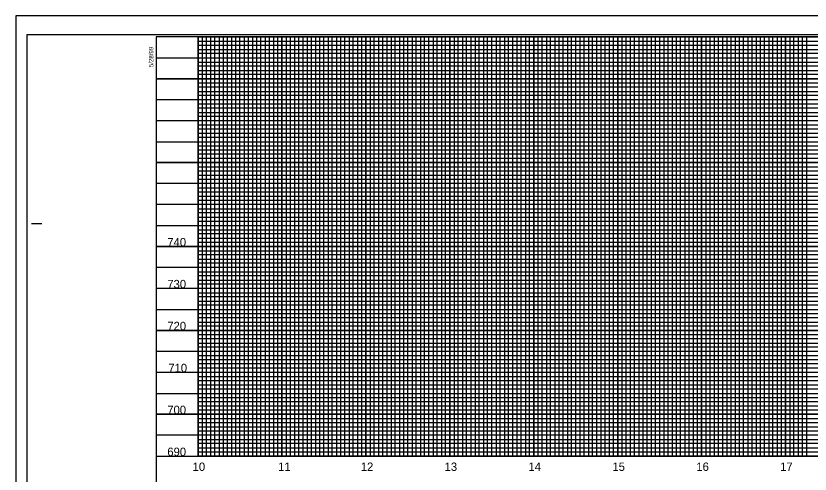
# Model space of a CAD drawing. Extents: x 1754992 to 1757273, y 732111 to 735411.
# Drawn here: x 1755181 to 1756127, y 734864 to 735411 of the extents above; entities that cross this region are included whole.
import ezdxf

# ---------------------------------------------------------------- set-up
doc = ezdxf.new("R2010")
doc.units = 0
for name, color, linetype in [('Prop DSN Text', 7, 'Continuous'), ('Scratch_Level_3', 7, 'Continuous'), ('Sheet Cutting Line CELL', 7, 'Continuous'), ('Sheet DOT Grid CELL', 7, 'Continuous'), ('Sheet Plot Border Inside CELL', 7, 'Continuous'), ('Sheet Plot Border Outside CELL', 7, 'Continuous'), ('Sheet Profile CELL', 7, 'Continuous'), ('Sheet Profile Grid Major CELL', 7, 'Continuous'), ('Sheet Profile Grid Middle CELL', 7, 'Continuous'), ('Sheet Profile Grid Minor CELL', 7, 'Continuous')]:
    doc.layers.add(name, color=color, linetype=linetype)

msp = doc.modelspace()

# ---------------------------------------------------------------- linework, layer by layer
at = {"layer": 'Scratch_Level_3'}
msp.add_lwpolyline([(1755397.67, 734885.78), (1755397.67, 735385.78), (1756647.62, 735385.78), (1756647.63, 735152.66), (1756797.67, 735152.66), (1756797.67, 734885.78)], close=True, dxfattribs=at)
at = {"layer": 'Sheet Cutting Line CELL'}
for p, q in [((1756864.67, 735410.78), (1755180.67, 735410.78)), ((1755180.67, 735410.78), (1755180.67, 734310.78))]:
    msp.add_line(p, q, dxfattribs=at)
at = {"layer": 'Sheet DOT Grid CELL'}
for p, q in [((1755397.67, 734885.78), (1755397.67, 735385.78)), ((1755447.67, 734885.78), (1755447.67, 735385.78)), ((1755497.67, 734885.78), (1755497.67, 735385.78)), ((1755547.67, 734885.78), (1755547.67, 735385.78)), ((1755597.67, 734885.78), (1755597.67, 735385.78)), ((1755647.67, 734885.78), (1755647.67, 735385.78)), ((1755697.67, 734885.78), (1755697.67, 735385.78)), ((1755747.67, 734885.78), (1755747.67, 735385.78)), ((1755797.67, 734885.78), (1755797.67, 735385.78)), ((1755847.67, 734885.78), (1755847.67, 735385.78)), ((1755897.67, 734885.78), (1755897.67, 735385.78)), ((1755947.67, 734885.78), (1755947.67, 735385.78)), ((1755997.67, 734885.78), (1755997.67, 735385.78)), ((1756047.67, 734885.78), (1756047.67, 735385.78)), ((1756097.67, 734885.78), (1756097.67, 735385.78)), ((1756647.62, 735335.78), (1755347.67, 735335.78)), ((1756647.62, 735285.78), (1755347.67, 735285.78)), ((1756647.67, 735235.78), (1755347.67, 735235.78)), ((1756647.63, 735185.78), (1755347.67, 735185.78)), ((1756847.67, 735135.78), (1755347.67, 735135.78)), ((1756847.67, 735085.78), (1755347.67, 735085.78)), ((1756847.67, 735035.78), (1755347.67, 735035.78)), ((1756847.67, 734985.78), (1755347.67, 734985.78)), ((1756847.67, 734935.78), (1755347.67, 734935.78))]:
    msp.add_line(p, q, dxfattribs=at)
at = {"layer": 'Sheet Plot Border Inside CELL'}
msp.add_lwpolyline([(1755193.67, 734333.23), (1756860.17, 734333.23), (1756860.17, 735388.33), (1755193.67, 735388.33)], close=True, dxfattribs=at)
at = {"layer": 'Sheet Plot Border Outside CELL'}
msp.add_lwpolyline([(1755180.67, 734310.78), (1756864.67, 734310.78), (1756864.67, 735410.78), (1755180.67, 735410.78)], close=True, dxfattribs=at)
at = {"layer": 'Sheet Profile CELL'}
for p, q in [((1755199.17, 735163.28), (1755211.67, 735163.28)), ((1755347.67, 734885.78), (1756847.67, 734885.78))]:
    msp.add_line(p, q, dxfattribs=at)
msp.add_lwpolyline([(1756847.67, 735385.78), (1755347.67, 735385.78), (1755347.67, 734335.78), (1756847.67, 734335.78)], close=True, dxfattribs=at)
at = {"layer": 'Sheet Profile Grid Major CELL'}
for points in [[(1755397.67, 735385.78), (1755397.67, 734885.78), (1755447.67, 734885.78), (1755447.67, 735385.78), (1755497.67, 735385.78), (1755497.67, 734885.78), (1755547.67, 734885.78), (1755547.67, 735385.78), (1755597.67, 735385.78), (1755597.67, 734885.78), (1755647.67, 734885.78), (1755647.67, 735385.78), (1755697.67, 735385.78), (1755697.67, 734885.78), (1755747.67, 734885.78), (1755747.67, 735385.78), (1755797.67, 735385.78), (1755797.67, 734885.78), (1755847.67, 734885.78), (1755847.67, 735385.78), (1755897.67, 735385.78), (1755897.67, 734885.78), (1755947.67, 734885.78), (1755947.67, 735385.78), (1755997.67, 735385.78), (1755997.67, 734885.78), (1756047.67, 734885.78), (1756047.67, 735385.78), (1756097.67, 735385.78), (1756097.67, 734885.78), (1756147.67, 734885.78)], [(1755347.67, 735335.78), (1756647.67, 735335.78)], [(1756647.67, 735285.78), (1755347.67, 735285.78), (1755347.67, 735235.78), (1756647.67, 735235.78)], [(1756647.63, 735185.78), (1755347.67, 735185.78), (1755347.67, 735135.78), (1756847.67, 735135.78)], [(1756847.67, 735085.78), (1755347.67, 735085.78), (1755347.67, 735035.78), (1756847.67, 735035.78)], [(1756847.67, 734985.78), (1755347.67, 734985.78), (1755347.67, 734985.78), (1755347.67, 734935.78), (1756847.67, 734935.78)]]:
    msp.add_lwpolyline(points, dxfattribs=at)
at = {"layer": 'Sheet Profile Grid Middle CELL'}
msp.add_line((1755347.67, 735360.78), (1756647.62, 735360.78), dxfattribs=at)
for points in [[(1755422.67, 735385.78), (1755422.67, 734885.78), (1755472.67, 734885.78), (1755472.67, 735385.78), (1755522.67, 735385.78), (1755522.67, 734885.78), (1755572.67, 734885.78), (1755572.67, 735385.78), (1755622.67, 735385.78), (1755622.67, 734885.78), (1755672.67, 734885.78), (1755672.67, 735385.78), (1755722.67, 735385.78), (1755722.67, 734885.78), (1755772.67, 734885.78), (1755772.67, 735385.78), (1755822.67, 735385.78), (1755822.67, 734885.78), (1755872.67, 734885.78), (1755872.67, 735385.78), (1755922.67, 735385.78), (1755922.67, 734885.78), (1755972.67, 734885.78), (1755972.67, 734885.78), (1755972.67, 735385.78), (1756022.67, 735385.78), (1756022.67, 734885.78), (1756072.67, 734885.78), (1756072.67, 735385.78), (1756122.67, 735385.78), (1756122.67, 734885.78), (1756172.67, 734885.78)], [(1756647.67, 735310.78), (1755347.67, 735310.78), (1755347.67, 735260.78), (1756647.67, 735260.78)], [(1756647.62, 735210.78), (1755347.67, 735210.78), (1755347.67, 735160.78), (1756647.63, 735160.78)], [(1756847.67, 735110.78), (1755347.67, 735110.78), (1755347.67, 735060.78), (1756847.67, 735060.78)], [(1756847.67, 735010.78), (1755347.67, 735010.78), (1755347.67, 734960.78), (1756847.67, 734960.78)], [(1756847.67, 734910.78), (1755347.67, 734910.78)]]:
    msp.add_lwpolyline(points, dxfattribs=at)
at = {"layer": 'Sheet Profile Grid Minor CELL'}
for p, q in [((1755397.67, 735380.78), (1756647.67, 735380.78)), ((1755397.67, 735375.78), (1755397.67, 735375.78)), ((1756647.67, 735375.78), (1755397.67, 735375.43)), ((1755397.67, 735370.78), (1756647.67, 735370.78)), ((1756647.62, 735250.78), (1755397.67, 735250.78)), ((1756647.67, 735245.78), (1755397.67, 735245.78)), ((1756647.67, 735240.78), (1755397.67, 735240.78)), ((1755397.67, 735230.78), (1756647.67, 735230.78)), ((1756647.67, 735225.78), (1755397.67, 735225.78)), ((1755397.67, 735220.78), (1756647.62, 735220.78)), ((1756647.62, 735200.78), (1755397.67, 735200.78)), ((1755397.67, 735195.78), (1756647.62, 735195.78)), ((1756647.63, 735175.78), (1755397.67, 735175.78)), ((1755397.67, 735170.78), (1756647.63, 735170.78)), ((1756797.67, 735150.78), (1755397.67, 735150.78)), ((1755397.67, 735145.78), (1756797.67, 735145.78)), ((1756797.67, 735140.78), (1755397.67, 735140.78)), ((1755397.67, 735130.78), (1756797.67, 735130.78)), ((1756797.67, 735125.78), (1755397.67, 735125.78)), ((1755397.67, 735120.78), (1756797.67, 735120.78)), ((1756797.67, 735115.78), (1755397.67, 735115.78)), ((1755397.67, 735105.78), (1756797.67, 735105.78)), ((1756797.67, 735100.78), (1755397.67, 735100.78)), ((1755397.67, 735095.78), (1756797.67, 735095.78)), ((1756797.67, 735090.78), (1755397.67, 735090.78)), ((1755397.67, 735080.78), (1756797.67, 735080.78)), ((1756797.67, 735075.78), (1755397.67, 735075.78)), ((1755397.67, 735070.78), (1756797.67, 735070.78)), ((1756797.67, 735065.78), (1755397.67, 735065.78)), ((1755397.67, 735055.78), (1756797.67, 735055.78)), ((1756797.67, 735050.78), (1755397.67, 735050.78)), ((1755397.67, 735045.78), (1756797.67, 735045.78)), ((1756797.67, 735040.78), (1755397.67, 735040.78)), ((1755397.67, 735030.78), (1756797.67, 735030.78)), ((1756797.67, 735025.78), (1755397.67, 735025.78)), ((1755397.67, 735020.78), (1756797.67, 735020.78)), ((1756797.67, 735015.78), (1755397.67, 735015.78)), ((1755397.67, 735005.78), (1756797.67, 735005.78)), ((1756797.67, 735000.78), (1755397.67, 735000.78)), ((1756797.67, 734995.78), (1755397.67, 734995.78)), ((1756797.67, 734990.78), (1755397.67, 734990.78)), ((1755397.67, 734980.78), (1756797.67, 734980.78)), ((1756797.67, 734975.78), (1755397.67, 734975.78)), ((1755397.67, 734970.78), (1756797.67, 734970.78)), ((1756797.67, 734965.78), (1755397.67, 734965.78)), ((1755397.67, 734955.78), (1756797.67, 734955.78)), ((1756797.67, 734950.78), (1755397.67, 734950.78)), ((1755397.67, 734945.78), (1756797.67, 734945.78)), ((1756797.67, 734940.78), (1755397.67, 734940.78)), ((1755397.67, 734930.78), (1756797.67, 734930.78)), ((1756797.67, 734925.78), (1755397.67, 734925.78)), ((1755397.67, 734920.78), (1756797.67, 734920.78)), ((1756797.67, 734915.78), (1755397.67, 734915.78)), ((1755397.67, 734905.78), (1756797.67, 734905.78)), ((1756797.67, 734900.78), (1755397.67, 734900.78)), ((1755397.67, 734895.78), (1756797.67, 734895.78))]:
    msp.add_line(p, q, dxfattribs=at)
for points in [[(1755402.67, 735385.78), (1755402.67, 734885.78), (1755407.67, 734885.78), (1755407.67, 735385.78), (1755412.67, 735385.78), (1755412.67, 734885.78), (1755417.67, 734885.78), (1755417.67, 735385.78), (1755427.67, 735385.78), (1755427.67, 734885.78), (1755432.67, 734885.78), (1755432.67, 735385.78), (1755437.67, 735385.78), (1755437.67, 734885.78), (1755442.67, 734885.78), (1755452.67, 734885.78), (1755457.67, 734885.78), (1755457.67, 735385.78), (1755462.67, 735385.78), (1755462.67, 734885.78), (1755467.67, 734885.78), (1755467.67, 735385.78), (1755477.67, 735385.78), (1755477.67, 734885.78), (1755482.67, 734885.78), (1755482.67, 735385.78), (1755487.67, 735385.78), (1755487.67, 734885.78), (1755492.67, 734885.78), (1755492.67, 735385.78), (1755502.67, 735385.78), (1755502.67, 734885.78), (1755507.67, 734885.78), (1755507.67, 735385.78), (1755512.67, 735385.78), (1755512.67, 734885.78), (1755517.67, 734885.78), (1755517.67, 735385.78), (1755527.67, 735385.78), (1755527.67, 734885.78), (1755532.67, 734885.78), (1755532.67, 735385.78), (1755537.67, 735385.78), (1755537.67, 734885.78), (1755542.67, 734885.78), (1755542.67, 735385.78), (1755552.67, 735385.78), (1755552.67, 734885.78), (1755557.67, 734885.78), (1755557.67, 735385.78), (1755562.67, 735385.78), (1755562.67, 734885.78), (1755567.67, 734885.78), (1755567.67, 735385.78), (1755577.67, 735385.78), (1755577.67, 734885.78), (1755582.67, 734885.78), (1755582.67, 735385.78), (1755587.67, 735385.78), (1755587.67, 734885.78), (1755592.67, 734885.78), (1755592.67, 735385.78), (1755602.67, 735385.78), (1755602.67, 734885.78), (1755607.67, 734885.78), (1755607.67, 735385.78), (1755612.67, 735385.78), (1755612.67, 734885.78)], [(1755442.67, 734885.78), (1755442.67, 735385.78), (1755452.67, 735385.78), (1755452.67, 734885.78)], [(1755612.67, 734885.78), (1755617.67, 734885.78), (1755617.67, 735385.78), (1755627.67, 735385.78), (1755627.67, 734885.78), (1755632.67, 734885.78), (1755632.67, 735385.78), (1755637.67, 735385.78), (1755637.67, 734885.78), (1755642.67, 734885.78), (1755642.67, 735385.78), (1755652.67, 735385.78), (1755652.67, 734885.78), (1755657.67, 734885.78), (1755657.67, 735385.78), (1755662.67, 735385.78), (1755662.67, 734885.78), (1755667.67, 734885.78), (1755667.67, 735385.78), (1755677.67, 735385.78), (1755677.67, 734885.78), (1755682.67, 734885.78), (1755682.67, 735385.78), (1755687.67, 735385.78), (1755687.67, 734885.78), (1755692.67, 734885.78), (1755692.67, 735385.78), (1755702.67, 735385.78), (1755702.67, 734885.78), (1755707.67, 734885.78), (1755707.67, 735385.78), (1755712.67, 735385.78), (1755712.67, 734885.78), (1755717.67, 734885.78), (1755717.67, 735385.78), (1755727.67, 735385.78), (1755727.67, 734885.78), (1755732.67, 734885.78), (1755732.67, 735385.78), (1755737.67, 735385.78), (1755737.67, 734885.78), (1755742.67, 734885.78), (1755742.67, 735385.78), (1755752.67, 735385.78), (1755752.67, 734885.78), (1755757.67, 734885.78), (1755757.67, 735385.78), (1755762.67, 735385.78), (1755762.67, 734885.78), (1755767.67, 734885.78), (1755767.67, 735385.78), (1755777.67, 735385.78), (1755777.67, 734885.78), (1755782.67, 734885.78), (1755782.67, 735385.78), (1755787.67, 735385.78), (1755787.67, 734885.78), (1755792.67, 734885.78), (1755792.67, 735385.78), (1755802.67, 735385.78), (1755802.67, 734885.78), (1755807.67, 734885.78), (1755807.67, 735385.78), (1755812.67, 735385.78), (1755812.67, 734885.78), (1755817.67, 734885.78), (1755817.67, 735385.78), (1755827.67, 735385.78), (1755827.67, 734885.78), (1755832.67, 734885.78), (1755832.67, 735385.78), (1755837.67, 735385.78), (1755837.67, 734885.78), (1755842.67, 734885.78), (1755842.67, 735385.78), (1755852.67, 735385.78), (1755852.67, 734885.78), (1755857.67, 734885.78), (1755857.67, 735385.78), (1755862.67, 735385.78), (1755862.67, 734885.78), (1755867.67, 734885.78), (1755867.67, 735385.78), (1755877.67, 735385.78), (1755877.67, 734885.78), (1755882.67, 734885.78), (1755882.67, 735385.78), (1755887.67, 735385.78), (1755887.67, 734885.78), (1755892.67, 734885.78), (1755892.67, 735385.78), (1755902.67, 735385.78), (1755902.67, 734885.78), (1755907.67, 734885.78), (1755907.67, 735385.78), (1755912.67, 735385.78), (1755912.67, 734885.78), (1755917.67, 734885.78), (1755917.67, 735385.78), (1755927.67, 735385.78)], [(1755927.67, 735385.78), (1755927.67, 734885.78), (1755932.67, 734885.78), (1755932.67, 735385.78), (1755937.67, 735385.78), (1755937.67, 734885.78), (1755942.67, 734885.78), (1755942.67, 735385.78), (1755952.67, 735385.78), (1755952.67, 734885.78), (1755957.67, 734885.78), (1755957.67, 735385.78), (1755962.67, 735385.78), (1755962.67, 734885.78), (1755967.67, 734885.78), (1755967.67, 735385.78), (1755977.67, 735385.78), (1755977.67, 734885.78), (1755982.67, 734885.78), (1755982.67, 735385.78), (1755987.67, 735385.78), (1755987.67, 734885.78), (1755992.67, 734885.78), (1755992.67, 735385.78), (1756002.67, 735385.78), (1756002.67, 734885.78), (1756007.67, 734885.78), (1756007.67, 735385.78), (1756012.67, 735385.78), (1756012.67, 734885.78), (1756017.67, 734885.78), (1756017.67, 735385.78), (1756027.67, 735385.78), (1756027.67, 734885.78), (1756032.67, 734885.78), (1756032.67, 735385.78), (1756037.67, 735385.78), (1756037.67, 734885.78), (1756042.67, 734885.78), (1756042.67, 735385.78), (1756052.67, 735385.78), (1756052.67, 734885.78), (1756052.67, 734885.78), (1756057.67, 734885.78), (1756057.67, 735385.78), (1756062.67, 735385.78), (1756062.67, 734885.78), (1756067.67, 734885.78), (1756067.67, 735385.78), (1756077.67, 735385.78), (1756077.67, 734885.78), (1756082.67, 734885.78), (1756082.67, 735385.78), (1756087.67, 735385.78), (1756087.67, 734885.78), (1756092.67, 734885.78), (1756092.67, 735385.78), (1756102.67, 735385.78), (1756102.67, 734885.78), (1756107.67, 734885.78), (1756107.67, 735385.78), (1756112.67, 735385.78), (1756112.67, 734885.78), (1756117.67, 734885.78), (1756117.67, 735385.78), (1756127.67, 735385.78)], [(1756647.67, 735365.78), (1755397.67, 735365.78), (1755397.67, 735355.78), (1756647.67, 735355.78)], [(1756647.62, 735350.78), (1755397.67, 735350.78), (1755397.67, 735345.78), (1756647.67, 735345.78)], [(1756647.67, 735340.78), (1755397.67, 735340.78), (1755397.67, 735330.78), (1756647.67, 735330.78)], [(1756647.67, 735325.78), (1755397.67, 735325.78), (1755397.67, 735320.78), (1756647.67, 735320.78)], [(1756647.67, 735315.78), (1755397.67, 735315.78), (1755397.67, 735305.78), (1756647.67, 735305.78)], [(1756647.67, 735300.78), (1755397.67, 735300.78), (1755397.67, 735295.78), (1756647.67, 735295.78)], [(1756647.67, 735290.78), (1755397.67, 735290.78), (1755397.67, 735280.78), (1756647.67, 735280.78)], [(1756647.67, 735275.68), (1755397.77, 735275.68), (1755397.77, 735270.78), (1756647.67, 735270.78)], [(1756647.67, 735265.78), (1755397.67, 735265.78), (1755397.67, 735255.78), (1756647.67, 735255.78)], [(1756647.62, 735215.78), (1755397.67, 735215.78), (1755397.67, 735205.78), (1756647.62, 735205.78)], [(1756647.62, 735190.78), (1755397.67, 735190.78), (1755397.67, 735180.78), (1756647.63, 735180.78)], [(1756647.63, 735165.78), (1755397.67, 735165.78), (1755397.67, 735155.78), (1756647.63, 735155.78)], [(1756797.67, 734890.78), (1755397.67, 734890.78)]]:
    msp.add_lwpolyline(points, dxfattribs=at)

# ---------------------------------------------------------------- texts
at = {"layer": 'Prop DSN Text'}
for s, p in [('740', (1755361.1, 735136.03)), ('730', (1755361.1, 735086.03)), ('720', (1755361.1, 735036.03)), ('710', (1755362.3, 734986.03)), ('700', (1755361.1, 734936.03)), ('690', (1755361.1, 734886.03))]:
    msp.add_text(s, height=10, dxfattribs=at).set_placement(p)
at = {"layer": 'Scratch_Level_3'}
for s, p in [('10', (1755391.25, 734868.28)), ('11', (1755493.09, 734868.28)), ('12', (1755591.64, 734868.28)), ('13', (1755691.48, 734868.28)), ('14', (1755791.32, 734868.28)), ('15', (1755891.41, 734868.28)), ('16', (1755991.35, 734868.28)), ('17', (1756091.21, 734868.28))]:
    msp.add_text(s, height=10, dxfattribs=at).set_placement(p)
at = {"layer": 'Sheet Profile CELL'}
msp.add_text('5/28/99', height=5.25, rotation=90, dxfattribs=at).set_placement((1755344.43, 735349.7))

doc.saveas('drawing.dxf')
